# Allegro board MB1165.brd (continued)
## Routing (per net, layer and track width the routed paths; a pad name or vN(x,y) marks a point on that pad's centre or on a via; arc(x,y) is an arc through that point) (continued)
D10: length 138.4
  TOP w0.102: v4(72.52,100.6) 72.91,100.99 75.08,100.99 75.33,101.23 75.33,102.79 75.53,102.99 76.53,102.99 U9.F4 ; U16.C2 66.8,75.15 66.8,76.58 66.29,77.09 66.29,78.23 ; v5(87.46,76.97) U15.M2
  TOP w0.127: v5(66.29,79.25) 66.29,78.23 ; R62.2 v1(68.58,121.28) ; CN10.19 v3(53.42,105.97)
  L3_SIG w0.102: v4(72.52,100.6) 72,101.12 71.53,101.12 71.37,100.97 70.64,100.97 70.12,101.49 69.97,101.49 69.52,101.03 69.38,101.03 69.23,101.18 69.23,101.32 69.68,101.77 69.68,101.92 69.54,102.06 69.4,102.06 68.94,101.61 68.8,101.61 68.66,101.75 68.66,101.9 69.11,102.35 69.11,102.49 68.97,102.64 68.82,102.64 68.37,102.18 68.23,102.18 68.08,102.33 68.08,102.47 68.53,102.92 68.53,103.07 68.39,103.21 68.25,103.21 67.79,102.76 67.65,102.76 67.51,102.9 67.51,103.05 67.96,103.5 67.96,103.64 67.82,103.79 67.67,103.79 67.22,103.33 67.08,103.33 66.93,103.48 66.93,103.62 67.38,104.07 67.38,104.22 67.24,104.36 67.1,104.36 66.64,103.91 66.5,103.91 66.36,104.05 66.36,104.2 66.81,104.65 66.81,104.79 66.67,104.94 66.52,104.94 66.07,104.48 65.93,104.48 65.78,104.63 65.78,104.77 66.23,105.22 66.23,105.37 65.05,106.55 54,106.55 v3(53.42,105.97) ; v5(87.46,76.97) 86.45,77.98 86.45,78.17 85.75,78.87 74.55,78.87 v1(74.42,78.74) 66.42,78.74 66.29,78.87 v5(66.29,79.25)
  BOTTOM w0.127: v4(72.52,100.6) 72.52,98.81 69.98,96.27 69.98,90.78 70.1,90.65 70.48,90.65 70.61,90.53 70.61,90.32 70.48,90.2 70.13,90.2 70,90.07 70,89.87 70.13,89.74 70.46,89.74 70.59,89.61 70.59,89.43 70.46,89.31 70.1,89.31 69.98,89.18 69.98,88.85 70.1,88.72 70.89,88.72 71.02,88.85 71.02,90.53 71.15,90.65 71.35,90.65 71.48,90.53 71.48,88.85 71.6,88.72 71.81,88.72 71.93,88.85 71.93,90.53 72.06,90.65 72.31,90.65 72.44,90.53 72.44,88.85 72.57,88.72 72.82,88.72 72.95,88.85 72.95,90.53 73.08,90.65 73.33,90.65 73.46,90.53 73.46,88.04 73.58,87.91 73.84,87.91 73.96,88.04 73.96,90.53 74.09,90.65 74.3,90.65 74.42,90.53 v1(74.42,78.74) ; v3(53.42,105.97) 54.13,106.68 57.91,106.68 68.58,117.35 v1(68.58,121.28)
D11: length 139.5
  TOP w0.102: U9.G4 75.52,103.76 73.51,103.76 72.77,103.02 72.77,102.11 72.11,101.45 72.11,101.09 71.88,100.86 ; U16.D2 66.04,75.16 66.04,76.71 65.9,76.85 65.9,78.23 ; v5(85.86,77.77) U15.P1
  TOP w0.127: 65.9,78.23 65.9,78.56 65.34,79.12 v5(65.28,79.12) ; CN10.20 v3(54.86,105.97) ; R52.2 v1(68.58,124.59) ; 71.88,100.86 v4(71.65,100.63)
  L3_SIG w0.102: v4(71.65,100.63) 71.6,100.58 69.37,100.58 63.98,105.97 v3(54.86,105.97) ; v5(85.86,77.77) 85.86,78.28 85.58,78.56 74.86,78.56 74.52,78.23 v1(73.66,78.23) 73.46,78.44 66.14,78.44 65.46,79.12 v5(65.28,79.12)
  BOTTOM w0.127: v1(68.58,124.59) 68.58,124.05 68.71,123.93 69.01,123.93 69.14,123.8 69.14,123.6 69.01,123.47 68.68,123.47 68.55,123.34 68.55,123.11 68.68,122.98 68.99,122.98 69.11,122.85 69.11,122.6 68.99,122.47 68.68,122.47 68.55,122.35 68.55,122.12 68.68,122 69.09,122 69.22,121.87 69.22,117.35 57.84,105.97 v3(54.86,105.97) ; v1(73.66,78.23) 72.72,78.23 72.59,78.36 72.59,78.59 72.72,78.71 73.43,78.71 73.56,78.84 73.56,79.1 73.43,79.22 72.31,79.22 72.19,79.35 72.19,79.6 72.31,79.73 73.43,79.73 73.56,79.86 73.56,84.68 73.43,84.81 71.3,84.81 71.17,84.94 71.17,85.19 71.3,85.32 73.43,85.32 73.56,85.45 73.56,85.72 73.43,85.85 70.28,85.85 70.15,85.98 70.15,86.23 70.28,86.36 73.1,86.36 73.23,86.49 73.23,86.77 73.1,86.89 69.34,86.89 69.22,87.02 69.22,87.27 69.34,87.4 72.11,87.4 72.24,87.53 72.24,87.78 72.11,87.91 69.34,87.91 69.22,88.04 69.22,96.65 69.52,96.95 69.52,97.13 69.22,97.43 69.22,97.61 69.4,97.79 69.58,97.79 69.88,97.49 70.06,97.49 70.24,97.67 70.24,97.85 69.36,98.72 69.36,98.9 69.54,99.08 69.72,99.08 70.6,98.21 70.78,98.21 70.98,98.41 70.98,98.59 70.11,99.47 70.11,99.65 70.29,99.83 70.47,99.83 71.34,98.95 71.52,98.95 71.7,99.13 71.7,99.31 70.83,100.19 70.83,100.37 71.09,100.63 v4(71.65,100.63)
D12: length 135.8
  TOP w0.102: v5(64.84,77.28) 65.28,76.83 65.28,75.17 U16.E2 ; v5(86.66,76.97) U15.N2 ; U9.F5 76.51,102.77 75.67,102.77 75.53,102.63 75.53,101.11 75.19,100.76 73.33,100.76 v4(73.15,100.58)
  TOP w0.127: CN10.17 v3(53.42,107.24) ; R61.2 v1(67.56,121.28)
  L3_SIG w0.102: v5(86.66,76.97) 86.4,76.97 86.03,77.34 84.84,77.34 84.51,77.67 75.74,77.67 75.59,77.52 v1(74.93,77.52) 74.81,77.4 72.95,77.4 72.85,77.51 72.85,77.72 72.75,77.83 72.55,77.83 72.44,77.72 72.44,77.51 72.34,77.4 64.96,77.4 v5(64.84,77.28) ; v3(53.42,107.24) 52.83,106.65 52.83,105.69 53.09,105.44 55.47,105.44 55.57,105.33 55.57,104.42 55.67,104.32 55.9,104.32 56,104.42 56,105.51 56.11,105.61 56.31,105.61 56.41,105.51 56.41,104.42 56.51,104.32 56.72,104.32 56.82,104.42 56.82,105.51 56.92,105.61 57.12,105.61 57.22,105.51 57.22,104.42 57.33,104.32 57.53,104.32 57.63,104.42 57.63,105.51 57.73,105.61 57.94,105.61 58.04,105.51 58.04,104.42 58.14,104.32 58.34,104.32 58.44,104.42 58.44,105.51 58.54,105.61 58.75,105.61 58.85,105.51 58.85,104.42 58.95,104.32 59.15,104.32 59.26,104.42 59.26,105.51 59.36,105.61 59.56,105.61 59.66,105.51 59.66,104.42 59.76,104.32 59.97,104.32 60.07,104.42 60.07,105.51 60.17,105.61 60.37,105.61 60.48,105.51 60.48,104.42 60.58,104.32 60.78,104.32 60.88,104.42 60.88,105.51 60.98,105.61 61.19,105.61 61.29,105.51 61.29,104.42 61.39,104.32 61.59,104.32 61.69,104.42 61.69,105.51 61.8,105.61 62,105.61 62.1,105.51 62.1,104.42 62.2,104.32 62.41,104.32 62.51,104.42 62.51,105.51 62.61,105.61 62.81,105.61 62.91,105.51 62.91,104.42 63.02,104.32 63.22,104.32 63.32,104.42 63.32,105.51 63.42,105.61 63.62,105.61 63.73,105.51 63.73,104.42 63.83,104.32 65.02,104.32 69.14,100.2 72.77,100.2 v4(73.15,100.58)
  BOTTOM w0.127: v1(74.93,77.52) 74.93,90.91 74.8,91.03 70.48,91.03 70.36,91.16 70.36,96.06 73.15,98.86 v4(73.15,100.58) ; v3(53.42,107.24) 54.13,107.95 57.91,107.95 66.78,116.81 66.78,116.99 66.35,117.42 66.35,117.6 66.53,117.78 66.71,117.78 67.14,117.35 67.32,117.35 67.56,117.6 v1(67.56,121.28)
D13: length 147.3
  TOP w0.102: 74.15,97.79 75.29,98.93 75.29,100.44 75.91,101.06 U9.G6 ; v5(85.06,77.77) 85.06,77.93 84.93,78.05 84.27,78.05 ; U15.R1 84.27,77.37 ; U16.F2 64.52,75.18 64.52,76.22 64.52,76.22 64.52,76.83 v5(64.14,77.22)
  TOP w0.127: 84.27,78.05 84.15,78.05 84.02,77.93 84.02,77.49 84.15,77.37 84.27,77.37 ; CN10.35 53.03,95.81 v3(53.42,96.2) ; v4(73.03,96.65) 73.41,97.03 73.41,97.05 74.15,97.79 ; R56.2 v1(75.18,124.71)
  L3_SIG w0.102: v5(85.06,77.77) 85.37,77.77 85.5,77.89 85.5,78.13 85.37,78.26 84.76,78.26 84.63,78.13 84.63,78.11 84.51,77.98 84.21,77.98 84.11,78.08 84.11,78.16 84,78.26 83.8,78.26 83.7,78.16 83.7,78.08 83.6,77.98 83.39,77.98 83.29,78.08 83.29,78.16 83.19,78.26 82.99,78.26 82.89,78.16 82.89,78.08 82.79,77.98 82.58,77.98 82.48,78.08 82.48,78.16 82.38,78.26 82.18,78.26 82.07,78.16 82.07,78.08 81.97,77.98 81.77,77.98 81.67,78.08 81.67,78.16 81.57,78.26 81.36,78.26 81.26,78.16 81.26,78.08 81.16,77.98 80.96,77.98 80.85,78.08 80.85,78.16 80.75,78.26 80.55,78.26 80.45,78.16 80.45,78.08 80.35,77.98 80.14,77.98 80.04,78.08 80.04,78.16 79.94,78.26 79.74,78.26 79.64,78.16 79.64,78.08 79.53,77.98 79.33,77.98 79.23,78.08 79.23,78.16 79.13,78.26 78.92,78.26 78.82,78.16 78.82,78.08 78.72,77.98 78.52,77.98 78.42,78.08 78.42,78.16 78.31,78.26 78.11,78.26 78.01,78.16 78.01,78.08 77.91,77.98 77.09,77.98 v1(76.96,78.11) 74.9,78.11 74.56,77.76 73.42,77.76 73.05,78.13 72.24,78.13 71.87,77.76 64.55,77.76 64.14,77.34 v5(64.14,77.22) ; v4(73.03,96.65) 69.9,96.65 69.77,96.52 69.77,95.94 69.65,95.81 66.47,95.81 66.34,95.68 66.34,94.54 66.22,94.41 66.03,94.41 65.91,94.54 65.91,95.66 65.81,95.76 65.6,95.76 65.5,95.66 65.5,94.51 65.4,94.41 65.2,94.41 65.09,94.51 65.09,95.66 64.99,95.76 64.79,95.76 64.69,95.66 64.69,94.51 64.59,94.41 64.38,94.41 64.28,94.51 64.28,95.66 64.18,95.76 63.98,95.76 63.87,95.66 63.87,94.51 63.77,94.41 63.57,94.41 63.47,94.51 63.47,95.66 63.37,95.76 63.16,95.76 63.06,95.66 63.06,94.51 62.96,94.41 62.76,94.41 62.66,94.51 62.66,95.66 62.55,95.76 62.35,95.76 62.25,95.66 62.25,94.51 62.15,94.41 61.94,94.41 61.84,94.51 61.84,95.66 61.74,95.76 61.54,95.76 61.44,95.66 61.44,94.51 61.33,94.41 61.13,94.41 61.03,94.51 61.03,95.66 60.93,95.76 60.73,95.76 60.62,95.66 60.62,94.51 60.52,94.41 60.32,94.41 60.22,94.51 60.22,95.66 60.12,95.76 59.91,95.76 59.81,95.66 59.81,94.51 59.71,94.41 59.51,94.41 59.4,94.51 59.4,95.66 59.3,95.76 59.1,95.76 59,95.66 59,94.51 58.9,94.41 58.69,94.41 58.59,94.51 58.59,95.66 58.49,95.76 58.29,95.76 58.19,95.66 58.19,94.51 58.08,94.41 57.88,94.41 57.78,94.51 57.78,95.66 57.68,95.76 53.85,95.76 v3(53.42,96.2)
  BOTTOM w0.127: v1(75.18,124.71) 75.18,123.83 74.8,123.44 74.8,121.64 74.42,121.25 74.42,114.55 56.62,96.75 53.98,96.75 53.42,96.2 v3(53.42,96.2) ; v4(73.03,96.65) 73.03,96.11 76.96,92.18 v1(76.96,78.11)
D14: length 139.9
  TOP w0.102: v5(86.66,76.17) U15.N3 ; U9.F6 76.29,100.75 76.29,98.39 75.69,97.79 ; U16.F1 v5(64.92,76.07)
  TOP w0.127: v3(53.47,95.21) 53.47,95 53.01,94.54 CN10.37 ; R65.2 73.79,122.28 75.31,120.75 v1(75.44,120.75) ; 75.69,97.79 v4(74.55,96.65)
  L3_SIG w0.102: v5(86.66,76.17) 86.97,76.17 87.1,76.29 87.1,76.45 86.97,76.58 84.61,76.58 84.18,77.01 82.12,77.01 81.99,76.89 81.99,76.48 81.86,76.35 81.69,76.35 81.56,76.48 81.56,76.89 81.43,77.01 81.28,77.01 81.15,76.89 81.15,76.48 81.03,76.35 77.6,76.35 77.46,76.49 v1(77.46,76.85) 77.27,76.66 71.78,76.66 71.64,76.8 65.39,76.8 64.92,76.32 v5(64.92,76.07) ; v4(74.55,96.65) 74.55,95.1 74.42,94.97 74.12,94.97 73.99,95.1 73.99,96.15 73.86,96.28 73.62,96.28 73.52,96.18 73.52,95 73.41,94.89 73.21,94.89 73.11,95 73.11,96.07 72.99,96.19 72.82,96.19 72.7,96.07 72.7,95 72.6,94.89 72.4,94.89 72.3,95 72.3,96.18 72.2,96.28 71.99,96.28 71.89,96.18 71.89,95 71.79,94.89 71.59,94.89 71.48,95 71.48,96.18 71.38,96.28 70.21,96.28 70.08,96.15 70.08,94.21 69.95,94.08 69.72,94.08 69.62,94.18 69.62,95.4 69.52,95.5 69.31,95.5 69.21,95.4 69.21,94.18 69.11,94.08 68.91,94.08 68.81,94.18 68.81,95.4 68.7,95.5 68.5,95.5 68.4,95.4 68.4,94.18 68.3,94.08 68.09,94.08 67.99,94.18 67.99,95.4 67.89,95.5 67.69,95.5 67.59,95.4 67.59,94.18 67.49,94.08 67.28,94.08 67.18,94.18 67.18,95.4 67.08,95.5 66.88,95.5 66.77,95.4 66.77,94.18 66.67,94.08 57.43,94.08 57.3,94.21 57.3,95.33 57.18,95.45 53.71,95.45 v3(53.47,95.21)
  BOTTOM w0.127: v1(75.44,120.75) 75.18,120.5 75.18,114.17 56.64,95.63 53.89,95.63 v3(53.47,95.21) ; v4(74.55,96.65) 74.42,96.52 74.42,95.86 77.85,92.43 77.85,77.24 v1(77.46,76.85)
D15: length 138.8
  TOP w0.102: U16.G1 v5(64.16,76.07) ; U9.G7 75.53,99.99 75.53,98.39 74.93,97.79 ; v5(85.06,76.97) U15.R2
  TOP w0.127: 74.93,97.79 v4(73.84,96.7) ; CN10.36 55.24,95.81 54.86,96.19 v3(54.86,96.24) ; R66.2 75.18,121.67 v1(75.44,121.41)
  L3_SIG w0.102: v5(64.16,76.07) 64.16,76.1 65.15,77.09 76.81,77.09 v1(76.96,77.24) 77.06,77.34 77.9,77.34 78,77.24 78,76.78 78.1,76.68 78.3,76.68 78.4,76.78 78.4,77.25 78.52,77.37 78.69,77.37 78.81,77.25 78.81,76.78 78.91,76.68 79.12,76.68 79.22,76.78 79.22,77.25 79.34,77.37 79.5,77.37 79.62,77.25 79.62,76.78 79.72,76.68 79.91,76.68 80.04,76.81 80.04,77.14 80.16,77.27 80.34,77.27 80.47,77.14 80.47,76.81 80.59,76.68 80.72,76.68 80.85,76.81 80.85,77.21 80.98,77.34 84.36,77.34 84.73,76.97 v5(85.06,76.97) ; v4(73.84,96.7) 73.84,96.94 73.71,97.07 69.6,97.07 69.47,96.94 69.47,96.32 69.34,96.19 69.19,96.19 69.06,96.32 69.06,96.88 68.94,97 68.76,97 68.63,96.88 68.63,96.32 68.5,96.19 68.33,96.19 68.22,96.29 68.22,96.98 68.12,97.08 67.92,97.08 67.82,96.98 67.82,96.29 67.72,96.19 67.51,96.19 67.41,96.29 67.41,96.98 67.31,97.08 67.11,97.08 67.01,96.98 67.01,96.29 66.9,96.19 66.7,96.19 66.6,96.29 66.6,96.98 66.5,97.08 66.29,97.08 66.19,96.98 66.19,96.29 66.09,96.19 65.89,96.19 65.79,96.29 65.79,96.98 65.68,97.08 65.48,97.08 65.38,96.98 65.38,96.29 65.28,96.19 65.08,96.19 64.97,96.29 64.97,96.98 64.87,97.08 64.67,97.08 64.57,96.98 64.57,96.29 64.47,96.19 64.26,96.19 64.16,96.29 64.16,96.98 64.06,97.08 63.86,97.08 63.75,96.98 63.75,96.18 63.64,96.06 63.47,96.06 63.35,96.18 63.35,96.98 63.25,97.08 63.04,97.08 62.94,96.98 62.94,96.18 62.82,96.06 62.65,96.06 62.54,96.18 62.54,96.98 62.43,97.08 62.23,97.08 62.13,96.98 62.13,96.18 62.01,96.06 61.84,96.06 61.72,96.18 61.72,96.98 61.62,97.08 61.42,97.08 61.32,96.98 61.32,96.18 61.2,96.06 61.03,96.06 60.91,96.18 60.91,96.98 60.81,97.08 60.6,97.08 60.5,96.98 60.5,96.21 60.38,96.09 60.22,96.09 60.1,96.21 60.1,96.98 60,97.08 59.79,97.08 59.69,96.98 59.69,96.23 59.57,96.11 59.4,96.11 59.28,96.23 59.28,96.98 59.18,97.08 58.98,97.08 58.88,96.98 58.88,96.18 58.76,96.06 58.59,96.06 58.47,96.18 58.47,96.98 58.37,97.08 58.17,97.08 58.06,96.98 58.06,96.21 57.95,96.09 57.78,96.09 57.66,96.21 57.66,96.98 57.56,97.08 57.35,97.08 57.25,96.98 57.25,96.18 57.13,96.06 56.96,96.06 56.85,96.18 56.85,96.98 56.74,97.08 56.54,97.08 56.44,96.98 56.44,96.18 56.32,96.06 56.15,96.06 56.03,96.18 56.03,96.83 55.91,96.95 55.75,96.95 55.63,96.83 55.63,96.24 55.5,96.11 54.99,96.11 v3(54.86,96.24)
  BOTTOM w0.127: v3(54.86,96.24) 55.09,96.01 56.48,96.01 74.8,114.33 74.8,120.9 75.31,121.41 v1(75.44,121.41) ; v1(76.96,77.24) 77.09,77.24 77.47,77.62 77.47,92.22 73.79,95.9 73.79,96.65 v4(73.84,96.7)
D16: length 122.6
  TOP w0.102: 93.85,70.09 93.85,71.37 U15.E8
  TOP w0.127: v5(95.25,68.33) 93.85,69.72 93.85,70.09 ; R53.1 70.99,124.84 v1(70.87,124.71) ; CN10.22 v3(54.86,104.7)
  L3_SIG w0.102: v5(95.25,68.33) 92.3,68.33 88.9,64.92 66.62,64.92 51.66,79.88 51.66,84.56 51.77,84.66 53.73,84.66 53.85,84.78 53.85,84.95 53.73,85.07 51.77,85.07 51.66,85.17 51.66,85.37 51.77,85.47 52.92,85.47 53.04,85.59 53.04,85.76 52.92,85.88 51.77,85.88 51.66,85.98 51.66,86.19 51.77,86.29 52.08,86.29 52.2,86.41 52.2,86.57 52.08,86.69 51.77,86.69 51.66,86.8 51.66,104.17 52.63,105.13 54.03,105.13 54.46,104.7 v3(54.86,104.7)
  BOTTOM w0.127: v1(70.87,124.71) 70.15,124.71 69.98,124.54 69.98,116.74 57.93,104.7 v3(54.86,104.7)
D17: length 125
  TOP w0.102: v5(94.66,72.17) U15.D7
  TOP w0.127: R54.1 v1(72.39,124.71) ; CN10.26 v3(54.86,102.16)
  L3_SIG w0.102: v5(94.66,72.17) 95.07,71.75 95.78,71.75 95.89,71.65 95.89,71.12 96.27,70.74 96.27,69.98 95.76,69.47 92.51,69.47 88.6,65.56 66.95,65.56 52.32,80.19 52.32,80.57 52.43,80.67 54.08,80.67 54.2,80.79 54.2,80.96 54.08,81.08 52.43,81.08 52.32,81.18 52.32,81.38 52.43,81.48 54.16,81.48 54.28,81.6 54.28,81.77 54.16,81.89 52.43,81.89 52.32,81.99 52.32,82.19 52.43,82.3 54.36,82.3 54.46,82.4 54.46,85.32 52.27,87.5 52.27,102.06 52.96,102.74 53.59,102.74 54.18,102.16 v3(54.86,102.16)
  BOTTOM w0.127: v1(72.39,124.71) 72.39,124.46 71.88,123.95 71.88,120.65 71.5,120.27 71.5,115.95 57.71,102.16 v3(54.86,102.16)
D18: length 121.2
  TOP w0.102: U15.D8 94.7,71.32 94.7,70.09
  TOP w0.127: R63.1 v1(70.99,121.28) ; CN10.24 v3(54.86,103.43) ; v5(95.22,68.96) 95.22,69.24 94.7,69.76 94.7,70.09
  L3_SIG w0.102: v5(95.22,68.96) 92.46,68.96 88.72,65.23 66.83,65.23 51.97,80.09 51.97,82.62 52.07,82.72 54.05,82.72 54.15,82.82 54.15,83.02 54.05,83.12 52.07,83.12 51.97,83.22 51.97,83.43 52.07,83.53 54.05,83.53 54.15,83.63 54.15,83.83 54.05,83.94 52.07,83.94 51.97,84.04 51.97,84.24 52.07,84.34 54.05,84.34 54.15,84.44 54.15,85.12 51.97,87.3 51.97,103.15 52.83,104.01 53.59,104.01 54.18,103.43 v3(54.86,103.43)
  BOTTOM w0.127: v3(54.86,103.43) 57.81,103.43 70.74,116.36 70.74,121.03 v1(70.99,121.28)
D19: length 120.8
  TOP w0.102: v5(95.86,70.1) U15.B9
  TOP w0.127: R64.1 72.39,120.4 72,120 v1(72,119.9) ; CN10.27 v3(53.42,100.89)
  L3_SIG w0.102: v3(53.42,100.89) 52.58,100.05 52.58,87.73 54.79,85.52 54.79,85.23 54.89,85.13 55.71,85.13 55.83,85.01 55.83,84.85 55.71,84.73 54.89,84.73 54.79,84.62 54.79,84.42 54.89,84.32 55.8,84.32 55.91,84.22 55.91,84.02 55.8,83.91 54.89,83.91 54.79,83.81 54.79,83.61 54.89,83.51 55.8,83.51 55.91,83.41 55.91,83.2 55.8,83.1 54.89,83.1 54.79,83 54.79,82.8 54.89,82.69 55.8,82.69 55.91,82.59 55.91,82.39 55.8,82.29 54.89,82.29 54.79,82.19 54.79,81.98 54.89,81.88 55.8,81.88 55.91,81.78 55.91,81.58 55.8,81.48 54.89,81.48 54.79,81.37 54.79,80.34 54.69,80.24 53.13,80.24 53.01,80.12 53.01,79.95 53.13,79.83 54.69,79.83 54.79,79.73 54.79,79.53 54.69,79.42 54,79.42 53.9,79.32 53.9,79.12 54,79.02 54.69,79.02 54.79,78.92 54.79,78.16 67.08,65.86 88.47,65.86 92.46,69.85 95.61,69.85 v5(95.86,70.1)
  BOTTOM w0.127: v3(53.42,100.89) 54.13,101.6 57.73,101.6 72,115.86 v1(72,119.9)
D20: length 125.2
  TOP w0.102: v5(95.46,71.37) U15.C8
  TOP w0.127: CN10.32 v3(54.86,98.35) ; R55.1 v1(73.79,124.71)
  L3_SIG w0.102: v3(54.86,98.35) 54.15,99.06 53.42,99.06 52.88,98.53 52.88,88.57 56.21,85.24 56.21,81.23 56.11,81.13 55.19,81.13 55.09,81.02 55.09,80.82 55.19,80.72 56.5,80.72 56.62,80.6 56.62,80.43 56.5,80.31 55.19,80.31 55.09,80.21 55.09,80.01 55.19,79.91 56.45,79.91 56.57,79.79 56.57,79.62 56.45,79.5 55.19,79.5 55.09,79.4 55.09,79.2 55.19,79.09 56.42,79.09 56.54,78.98 56.54,78.81 56.42,78.69 55.19,78.69 55.09,78.59 55.09,78.38 55.19,78.28 56.36,78.28 56.54,78.11 56.54,76.91 67.21,66.24 88.37,66.24 92.25,70.13 92.25,71.48 92.38,71.6 92.66,71.6 92.79,71.48 92.79,70.82 92.91,70.69 93.17,70.69 93.29,70.82 93.29,71.48 93.42,71.6 93.63,71.6 93.76,71.48 93.76,70.76 93.86,70.66 94.06,70.66 94.16,70.76 94.16,71.51 94.28,71.63 94.45,71.63 94.57,71.51 94.57,70.76 94.67,70.66 94.88,70.66 94.98,70.76 94.98,71.27 95.08,71.37 v5(95.46,71.37)
  BOTTOM w0.127: v1(73.79,124.71) 73.79,124.15 73.27,123.63 73.27,115.44 56.18,98.35 v3(54.86,98.35)
D21: length 122.5
  TOP w0.102: v5(97.06,70.57) U15.A9
  TOP w0.127: v3(101.78,92.61) 101.78,92.6 101.11,93.27 CN11.39
  L3_SIG w0.102: v3(101.78,92.61) 102.87,91.52 102.87,90.81 98.93,86.87 98.93,83.97 98.81,83.85 97.79,83.85 97.66,83.72 97.66,73.38 96.65,72.36 96.65,70.98 v5(97.06,70.57)
  BOTTOM w0.127: R266.1 80.64,124.59 80.11,124.05 80.11,120.97 79.98,120.84 78.95,120.84 78.23,120.84 78.11,120.72 78.11,120.46 78.23,120.34 79.98,120.34 80.11,120.21 80.11,119.95 79.98,119.83 78.18,119.83 78.05,119.7 78.05,119.45 78.18,119.32 79.98,119.32 80.11,119.19 80.11,118.94 79.98,118.81 78.18,118.81 78.05,118.68 78.05,118.43 78.18,118.3 79.98,118.3 80.11,118.18 80.11,117.92 79.98,117.8 78.18,117.8 78.05,117.67 78.05,117.41 78.18,117.29 79.98,117.29 80.11,117.16 80.11,116.91 79.98,116.78 78.18,116.78 78.05,116.65 78.05,116.4 78.18,116.27 79.98,116.27 80.11,116.14 80.11,115.89 79.98,115.76 78.18,115.76 78.05,115.64 78.05,112.52 77.93,112.39 76.45,112.39 76.33,112.27 76.33,111.89 76.45,111.76 77.93,111.76 78.05,111.63 78.05,111.38 77.93,111.25 76.2,111.25 76.07,111.12 76.07,110.82 76.2,110.69 78.49,110.69 78.61,110.82 78.61,111.25 78.74,111.38 79.1,111.38 79.22,111.25 79.22,110.74 79.35,110.62 79.6,110.62 79.73,110.74 79.73,111.25 79.86,111.38 80.79,111.38 80.92,111.25 80.92,110.74 81.05,110.62 81.3,110.62 81.43,110.74 81.43,111.25 81.55,111.38 81.81,111.38 81.93,111.25 81.93,110.31 82.06,110.19 82.44,110.19 82.57,110.31 82.57,111.15 82.69,111.28 82.95,111.28 83.08,111.15 83.08,110.74 83.2,110.62 83.52,110.62 83.75,110.38 83.75,110.2 83.59,110.04 83.59,109.86 83.77,109.68 83.95,109.68 84.23,109.96 84.41,109.96 84.58,109.78 84.58,109.6 84.31,109.32 84.31,109.14 84.49,108.96 84.67,108.96 84.83,109.12 85.34,109.12 85.83,108.64 85.83,108.25 85.7,108.13 85.19,108.13 85.06,108 85.06,107.75 85.19,107.62 85.7,107.62 85.83,107.49 85.83,105.38 85.95,105.25 87.22,105.25 87.35,105.12 87.35,104.87 87.22,104.74 85.95,104.74 85.83,104.61 85.83,104.32 86,104.14 87.22,104.14 87.35,104.02 87.35,92.71 87.45,92.61 v3(101.78,92.61)
D22: length 118.6
  TOP w0.102: v5(95.46,72.17) U15.C7
  TOP w0.127: v3(103.5,95) 103.96,94.54 CN11.38
  L3_SIG w0.102: v3(103.5,95) 103,95.5 101.73,95.5 99.77,93.55 99.77,93.19 100.53,92.43 100.53,92.08 97.43,88.98 97.43,85.85 97.31,85.72 96.83,85.72 96.7,85.6 96.7,75.5 96.8,75.4 97.1,75.4 97.21,75.3 97.21,75.1 97.1,74.99 96.8,74.99 96.7,74.89 96.7,74.69 96.8,74.59 97.1,74.59 97.21,74.49 97.21,74.28 97.1,74.18 96.8,74.18 96.7,74.08 96.7,73.41 v5(95.46,72.17)
  BOTTOM w0.127: v3(103.5,95) 103.89,94.61 103.89,93.47 103.25,92.84 102.26,92.84 101.85,93.24 101.52,93.24 101.37,93.09 87.88,93.09 87.76,93.22 87.76,93.45 87.88,93.57 89.36,93.57 89.48,93.7 89.48,94.04 89.36,94.17 87.88,94.17 87.76,94.29 87.76,94.55 87.88,94.67 89.36,94.67 89.48,94.8 89.48,95.05 89.36,95.18 87.88,95.18 87.76,95.31 87.76,95.56 87.88,95.69 89.36,95.69 89.48,95.82 89.48,96.07 89.36,96.2 87.88,96.2 87.76,96.32 87.76,96.58 87.88,96.71 89.36,96.71 89.48,96.83 89.48,101.52 89.36,101.65 87.91,101.65 87.78,101.78 87.78,105.28 87.39,105.67 86.39,105.67 86.26,105.8 86.26,108.81 83.29,111.79 78.56,111.79 78.44,111.91 78.44,112.17 78.56,112.29 82.3,112.29 82.42,112.42 82.42,112.65 82.3,112.78 78.56,112.78 78.44,112.9 78.44,113.2 78.56,113.33 80.75,113.33 80.87,113.45 80.87,113.71 80.75,113.84 78.56,113.84 78.44,113.96 78.44,114.22 78.56,114.34 80.72,114.34 80.85,114.47 80.85,114.72 80.72,114.85 78.56,114.85 78.44,114.98 78.44,115.23 78.56,115.36 80.52,115.36 80.64,115.49 R276.1
D23: length 118.5
  TOP w0.102: v5(97.06,71.37) U15.A8
  TOP w0.127: CN11.36 103.71,95.81 v3(103.5,96.01)
  L3_SIG w0.102: v5(97.06,71.37) 98.04,72.35 98.04,83.36 98.17,83.49 99.16,83.49 99.29,83.62 99.29,86.59 104.17,91.47 104.17,95.61 103.76,96.01 v3(103.5,96.01)
  BOTTOM w0.127: v3(103.5,96.01) 103.38,96.01 102.87,95.5 101.22,95.5 101.09,95.38 101.09,94.03 100.97,93.9 98.41,93.9 98.29,94.03 98.29,95.38 98.16,95.5 97.91,95.5 97.78,95.38 97.78,94.03 97.65,93.9 97.4,93.9 97.27,94.03 97.27,95.38 97.14,95.5 96.89,95.5 96.76,95.38 96.76,94.03 96.64,93.9 96.38,93.9 96.25,94.03 96.25,95.38 96.13,95.5 95.87,95.5 95.75,95.38 95.75,94.03 95.62,93.9 95.37,93.9 95.24,94.03 95.24,95.38 95.11,95.5 94.86,95.5 94.73,95.38 94.73,94.03 94.6,93.9 94.35,93.9 94.22,94.03 94.22,95.38 94.1,95.5 93.84,95.5 93.71,95.38 93.71,94.03 93.59,93.9 93.33,93.9 93.21,94.03 93.21,95.38 93.08,95.5 92.83,95.5 92.7,95.38 92.7,94.03 92.57,93.9 92.32,93.9 92.19,94.03 92.19,95.38 92.06,95.5 91.11,95.5 90.98,95.63 90.98,102.44 90.86,102.56 90.4,102.56 90.27,102.69 90.27,102.94 90.4,103.07 90.86,103.07 90.98,103.2 90.98,103.89 90.86,104.01 90.09,104.01 89.97,104.14 89.97,104.42 90.09,104.55 90.63,104.55 90.76,104.67 90.76,104.95 90.63,105.08 90.09,105.08 89.97,105.21 89.97,105.46 90.09,105.59 90.71,105.59 91.06,105.94 91.06,106.12 90.88,106.3 90.7,106.3 90.4,106 90.22,106 90.04,106.18 90.04,106.36 90.34,106.66 90.34,106.84 90.16,107.02 89.98,107.02 89.68,106.72 89.5,106.72 89.32,106.89 89.32,107.07 89.62,107.38 89.62,107.56 89.44,107.74 89.26,107.74 88.96,107.43 88.78,107.43 88.6,107.61 88.6,107.79 88.9,108.1 88.9,108.28 88.72,108.46 88.54,108.46 88.24,108.15 88.06,108.15 87.88,108.33 87.88,108.51 88.19,108.81 88.19,108.99 88.01,109.17 87.83,109.17 87.52,108.87 87.34,108.87 87.16,109.05 87.16,109.23 87.47,109.53 87.47,109.71 87.29,109.89 87.11,109.89 86.8,109.59 86.62,109.59 86.45,109.77 86.45,109.95 86.75,110.25 86.75,110.43 86.57,110.61 86.39,110.61 86.09,110.31 85.91,110.31 85.73,110.49 85.73,110.67 86.03,110.97 86.03,111.15 85.85,111.33 85.67,111.33 85.37,111.03 85.19,111.03 85.01,111.21 85.01,111.39 85.31,111.69 85.31,111.87 85.13,112.05 84.95,112.05 84.65,111.75 84.47,111.75 84.29,111.93 84.29,112.11 84.59,112.41 84.59,112.59 84.41,112.77 84.23,112.77 83.93,112.47 83.75,112.47 83.57,112.65 83.57,112.83 83.87,113.13 83.87,113.31 83.69,113.49 83.51,113.49 83.21,113.18 83.03,113.18 82.85,113.36 82.85,113.54 83.15,113.85 83.15,114.03 82.52,114.66 82.52,115.49 82.4,115.62 81.81,115.62 81.69,115.75 81.69,116 81.81,116.13 82.4,116.13 82.52,116.26 82.52,116.51 82.4,116.64 81.81,116.64 81.69,116.76 81.69,117.02 81.81,117.14 82.4,117.14 82.52,117.27 82.52,117.53 82.4,117.65 81.81,117.65 81.69,117.78 81.69,118.03 81.81,118.16 82.4,118.16 82.52,118.29 82.52,118.54 82.4,118.67 81.81,118.67 81.69,118.8 81.69,119.05 81.81,119.18 82.4,119.18 82.52,119.3 82.52,119.56 82.4,119.68 81.81,119.68 81.69,119.81 81.69,120.07 81.81,120.19 82.4,120.19 82.52,120.32 82.52,120.57 82.4,120.7 81.81,120.7 81.69,120.83 81.69,121.08 81.81,121.21 82.4,121.21 82.52,121.34 82.52,121.69 82.42,121.79 R275.1
D24: length 124.1
  TOP w0.127: U15.A2 97.2,77.11 v5(97.28,77.11) ; CN11.37 101.52,94.54 101.85,94.87 101.85,94.88 v3(101.98,95.01)
  L3_SIG w0.102: v3(101.98,95.01) 101.94,95.01 100.91,93.97 100.91,93.83 101.46,93.27 101.46,93.1 101.34,92.98 101.17,92.98 100.62,93.54 100.47,93.54 100.33,93.4 100.33,93.25 102.51,91.07 102.51,90.96 102.25,90.69 102.11,90.69 100.94,91.86 100.8,91.86 100.66,91.71 100.66,91.57 101.82,90.41 101.82,90.26 101.68,90.12 101.53,90.12 100.37,91.28 100.22,91.28 100.08,91.14 100.08,91 101.24,89.83 101.24,89.69 101.1,89.54 100.96,89.54 99.79,90.71 99.65,90.71 99.51,90.56 99.51,90.42 100.67,89.26 100.67,89.11 100.53,88.97 100.38,88.97 99.22,90.13 99.07,90.13 98.93,89.99 98.93,89.85 100.09,88.68 100.09,88.54 99.95,88.39 99.81,88.39 98.64,89.56 98.5,89.56 98.35,89.41 98.35,89.27 99.52,88.11 99.52,87.96 99.38,87.82 99.23,87.82 98.07,88.98 97.92,88.98 97.78,88.84 97.78,88.7 98.94,87.53 98.94,87.39 98.6,87.05 98.6,85.45 98.48,85.32 97.16,85.32 97.03,85.19 97.03,77.36 v5(97.28,77.11)
  BOTTOM w0.127: R265.1 82.17,125.09 82.17,123.95 81.28,123.06 81.28,114.38 86.66,108.99 86.66,108.31 86.79,108.18 87.43,108.18 87.55,108.05 87.55,107.8 87.43,107.67 86.79,107.67 86.66,107.54 86.66,107.29 86.79,107.16 88.49,107.16 88.62,107.04 88.62,106.78 88.49,106.65 86.79,106.65 86.66,106.53 86.66,106.22 86.79,106.1 89.41,106.1 89.53,105.97 89.53,105.66 89.41,105.54 88.32,105.54 88.19,105.41 88.19,105.16 88.32,105.03 89.41,105.03 89.53,104.9 89.53,104.65 89.41,104.52 88.32,104.52 88.19,104.39 88.19,104.14 88.32,104.01 89.41,104.01 89.53,103.89 89.53,103.63 89.41,103.51 88.32,103.51 88.19,103.38 88.19,103.12 88.32,103 89.41,103 89.53,102.87 89.53,102.62 89.41,102.49 88.32,102.49 88.19,102.36 88.19,102.16 88.32,102.03 90.42,102.03 90.55,101.9 90.55,100.92 90.42,100.79 90.02,100.79 89.89,100.67 89.89,100.41 90.02,100.29 90.45,100.29 90.58,100.16 90.58,99.9 90.45,99.78 90.02,99.78 89.89,99.65 89.89,99.4 90.02,99.27 90.45,99.27 90.58,99.14 90.58,98.89 90.45,98.76 90.02,98.76 89.89,98.63 89.89,98.38 90.02,98.25 90.45,98.25 90.58,98.13 90.58,97.87 90.45,97.75 90.02,97.75 89.89,97.62 89.89,97.36 90.02,97.24 90.45,97.24 90.58,97.11 90.58,96.86 90.45,96.73 90.02,96.73 89.89,96.6 89.89,96.35 90.02,96.22 90.45,96.22 90.58,96.09 90.58,95.84 90.45,95.71 90.02,95.71 89.89,95.59 89.89,95.33 90.02,95.21 90.45,95.21 90.58,95.08 90.58,94.82 90.45,94.7 90.02,94.7 89.89,94.57 89.89,94.32 90.02,94.19 90.45,94.19 90.58,94.06 90.58,93.62 90.7,93.5 90.97,93.5 91.1,93.62 91.1,95 91.23,95.12 91.48,95.12 91.61,95 91.61,93.62 91.74,93.5 101.22,93.5 101.47,93.75 101.47,94.92 101.55,95 101.97,95 v3(101.98,95.01)
D25: length 122.8
  TOP w0.102: v5(95.46,76.17) U15.C3
  TOP w0.127: v3(101.98,96.01) 101.78,95.81 CN11.35
  L3_SIG w0.102: v3(101.98,96.01) 101.7,96.01 99.34,93.65 99.34,93.14 99.97,92.51 99.97,92 97.09,89.12 97.09,86.18 96.96,86.06 96.42,86.06 96.29,85.93 96.29,77.5 95.9,77.12 95.9,74.4 95.78,74.27 95.59,74.27 95.46,74.4 v5(95.46,76.17)
  BOTTOM w0.127: v3(101.98,96.01) 101.3,96.01 101.17,96.14 101.17,96.6 101.04,96.72 100.79,96.72 100.66,96.6 100.66,94.44 100.53,94.31 100.18,94.31 100.05,94.44 100.05,97.71 99.92,97.84 99.67,97.84 99.54,97.71 99.54,94.44 99.42,94.31 98.88,94.31 98.76,94.44 98.76,98.73 98.63,98.86 98.35,98.86 98.22,98.73 98.22,96.14 98.09,96.01 97.78,96.01 97.65,96.14 97.65,98.76 97.52,98.88 97.27,98.88 97.14,98.76 97.14,96.14 97.01,96.01 96.76,96.01 96.63,96.14 96.63,98.76 96.51,98.88 96.25,98.88 96.13,98.76 96.13,96.14 96,96.01 95.74,96.01 95.62,96.14 95.62,98.76 95.49,98.88 95.24,98.88 95.11,98.76 95.11,96.14 94.98,96.01 94.73,96.01 94.6,96.14 94.6,98.76 94.47,98.88 94.22,98.88 94.09,98.76 94.09,96.14 93.97,96.01 93.71,96.01 93.59,96.14 93.59,98.76 93.46,98.88 93.2,98.88 93.08,98.76 93.08,96.14 92.95,96.01 92.7,96.01 92.57,96.14 92.57,98.76 92.44,98.88 92.19,98.88 92.06,98.76 92.06,96.14 91.93,96.01 91.59,96.01 91.47,96.14 91.47,106.3 82.93,114.83 82.93,124.71 R264.1
D26: length 122.6
  TOP w0.127: CN11.33 v3(102.03,97.08) ; v1(98.55,77.22) 98.17,77.6 96.9,77.6 96.67,77.37 U15.A1
  L3_SIG w0.102: v1(98.55,77.22) 98.55,82.09 98.68,82.22 99.44,82.22 99.57,82.35 99.57,82.55 99.44,82.68 98.53,82.68 98.4,82.8 98.4,83.01 98.53,83.13 99.56,83.13 99.68,83.26 99.68,86.53 104.6,91.44 104.6,99.69 104.47,99.82 104.22,99.82 104.09,99.69 104.09,97.87 103.96,97.74 103.07,97.74 102.95,97.61 102.95,97.21 102.82,97.08 v3(102.03,97.08)
  BOTTOM w0.127: v3(102.03,97.08) 101.8,97.08 96.6,102.29 95.59,102.29 95.46,102.41 95.46,103.58 95.33,103.71 95.08,103.71 94.95,103.58 94.95,102.41 94.83,102.29 94.57,102.29 94.45,102.41 94.45,104.6 94.32,104.72 94.06,104.72 93.94,104.6 93.94,102.41 93.81,102.29 93.56,102.29 93.43,102.41 93.43,105.74 93.3,105.87 93.05,105.87 92.92,105.74 92.92,102.39 92.79,102.26 92.35,102.26 92.23,102.39 92.23,106.65 86.49,112.39 86.49,112.84 86.36,112.97 85.9,112.97 85.78,113.1 85.78,113.35 85.9,113.48 86.49,113.48 86.61,113.61 86.61,113.86 86.49,113.99 86.13,113.99 86,114.11 86,114.37 86.13,114.5 86.49,114.5 86.61,114.62 86.61,114.88 86.49,115 84.07,115 83.95,115.13 83.95,115.38 84.07,115.51 86.49,115.51 86.61,115.64 86.61,115.89 86.49,116.02 84.1,116.02 83.97,116.15 83.97,116.4 84.1,116.53 86.49,116.53 86.61,116.65 86.61,116.91 86.49,117.04 84.1,117.04 83.97,117.16 83.97,117.42 84.1,117.54 86.49,117.54 86.61,117.67 86.61,117.92 86.49,118.05 84.07,118.05 83.95,118.18 83.95,118.43 84.07,118.56 86.49,118.56 86.61,118.69 86.61,118.94 86.49,119.07 84.07,119.07 83.95,119.19 83.95,119.45 84.07,119.58 86.49,119.58 86.61,119.7 86.61,119.96 86.49,120.08 84.07,120.08 83.95,120.21 83.95,120.46 84.07,120.59 86.49,120.59 86.61,120.72 86.61,120.93 86.49,121.06 84.45,121.06 84.33,121.18 84.33,124.71 R263.1
D27: length 118.9
  TOP w0.102: v5(95.46,76.97) U15.C2
  TOP w0.127: CN11.34 v3(103.5,97.08)
  L3_SIG w0.102: v3(103.5,97.08) 103.5,96.75 103.28,96.52 101.53,96.52 101.1,96.95 100.96,96.95 100.81,96.8 100.81,96.66 101.26,96.22 101.26,96.07 101.11,95.93 100.97,95.93 100.53,96.37 100.38,96.37 100.24,96.23 100.24,96.08 100.68,95.64 100.68,95.5 100.54,95.35 100.39,95.35 99.95,95.8 99.81,95.8 99.66,95.65 99.66,95.51 100.11,95.07 100.11,94.92 99.96,94.78 99.82,94.78 99.38,95.22 99.23,95.22 99.09,95.08 99.09,94.93 99.53,94.49 99.53,94.35 99.39,94.2 99.24,94.2 98.8,94.65 98.66,94.65 98.51,94.5 98.51,94.36 98.96,93.92 98.96,93.77 98.81,93.63 98.67,93.63 98.23,94.07 98.08,94.07 97.94,93.93 97.94,93.78 99.45,92.27 99.45,91.94 99.29,91.77 99.14,91.77 97.74,93.17 97.59,93.17 97.45,93.03 97.45,92.89 98.85,91.48 98.85,91.34 98.71,91.19 98.57,91.19 97.16,92.6 97.02,92.6 96.87,92.45 96.87,92.31 98.28,90.9 98.28,90.76 98.14,90.62 97.99,90.62 96.59,92.02 96.44,92.02 96.3,91.88 96.3,91.74 97.7,90.33 97.7,90.19 96.99,89.47 94.77,89.47 94.67,89.37 94.67,89.16 94.77,89.06 95.83,89.06 95.94,88.96 95.94,88.76 95.83,88.65 94.77,88.65 94.67,88.55 94.67,88.35 94.77,88.25 95.83,88.25 95.94,88.15 95.94,87.94 95.83,87.84 94.77,87.84 94.67,87.74 94.67,87.54 94.77,87.43 95.83,87.43 95.94,87.33 95.94,77.67 95.46,77.2 v5(95.46,76.97)
  BOTTOM w0.127: v3(103.5,97.08) 103.05,97.08 102.49,96.52 101.8,96.52 98.98,99.34 98.08,99.34 97.95,99.47 97.95,100.3 97.82,100.43 97.57,100.43 97.44,100.3 97.44,99.47 97.32,99.34 97.06,99.34 96.94,99.47 96.94,101.17 96.81,101.3 96.55,101.3 96.43,101.17 96.43,99.47 96.3,99.34 96.05,99.34 95.92,99.47 95.92,101.63 95.79,101.75 95.54,101.75 95.41,101.63 95.41,99.47 95.28,99.34 95.03,99.34 94.9,99.47 94.9,101.63 94.78,101.75 94.52,101.75 94.4,101.63 94.4,99.47 94.27,99.34 94.01,99.34 93.89,99.47 93.89,101.63 93.76,101.75 93.51,101.75 93.38,101.63 93.38,99.47 93.25,99.34 93,99.34 92.87,99.47 92.87,101.63 92.74,101.75 92.49,101.75 92.36,101.63 92.36,99.47 92.24,99.34 91.97,99.34 91.85,99.47 91.85,106.48 83.36,114.96 83.36,121.01 83.57,121.21 R274.1
D28: length 118
  TOP w0.127: U15.B1 96.6,78.11 98.6,78.11 99.42,77.29 v5(99.42,77.27) ; CN11.22 v3(103.38,104.7)
  L3_SIG w0.102: v3(103.38,104.7) 103.73,104.7 103.86,104.57 103.86,102.52 103.96,102.41 105.32,102.41 105.44,102.3 105.44,102.13 105.32,102.01 103.96,102.01 103.86,101.91 103.86,101.7 103.96,101.6 105.31,101.6 105.41,101.5 105.41,101.3 105.31,101.2 103.96,101.2 103.86,101.09 103.86,100.79 103.99,100.66 105.23,100.66 105.36,100.53 105.36,87.02 105.23,86.89 105.04,86.89 104.92,87.02 104.92,90.2 104.8,90.32 104.63,90.32 104.51,90.2 104.51,86.68 104.39,86.56 104.22,86.56 104.1,86.68 104.1,89.47 103.98,89.59 103.82,89.59 103.7,89.47 103.7,85.36 103.58,85.24 103.41,85.24 103.29,85.36 103.29,88.73 103.17,88.85 103,88.85 102.88,88.73 102.88,84.65 102.77,84.53 102.6,84.53 102.48,84.65 102.48,87.89 102.36,88.01 102.19,88.01 102.07,87.89 102.07,84.55 101.95,84.43 101.78,84.43 101.67,84.55 101.67,86.98 101.55,87.1 101.38,87.1 101.26,86.98 101.26,84.52 101.14,84.4 100.97,84.4 100.85,84.52 100.85,86.22 100.73,86.33 100.56,86.33 100.45,86.22 100.45,82.23 99.42,81.2 v5(99.42,77.27)
  BOTTOM w0.127: R247.1 90.3,133.6 90.3,126.24 90.81,125.73 90.81,114.65 101.37,104.09 102.44,104.09 103.05,104.7 v3(103.38,104.7)
D29: length 119.4
  TOP w0.102: 97.73,75.06 95.12,75.06 94.61,75.56 94.61,76.21 U15.D2
  TOP w0.127: CN11.18 v3(103.38,107.24) ; v1(98.81,76.2) 98.81,75.82 98.04,75.06 97.73,75.06
  L3_SIG w0.102: v3(103.38,107.24) 104.83,107.24 106.4,105.66 106.4,88.82 107.11,88.11 107.11,84.02 106.4,83.31 106.4,78.87 106.27,78.74 105.94,78.74 105.81,78.61 105.81,78.38 105.91,78.28 106.38,78.28 106.48,78.18 106.48,77.98 106.38,77.88 105.91,77.88 105.81,77.77 105.81,77.57 105.91,77.47 106.38,77.47 106.48,77.37 106.48,77.17 106.38,77.06 105.91,77.06 105.81,76.96 105.81,75.36 105.71,75.26 105.5,75.26 105.4,75.36 105.4,76.87 105.28,76.99 105.12,76.99 105,76.87 105,75.36 104.9,75.26 104.69,75.26 104.59,75.36 104.59,75.8 104.47,75.92 104.3,75.92 104.18,75.8 104.18,75.36 104.08,75.26 103.94,75.26 103.81,75.39 103.81,78.62 103.69,78.74 103.52,78.74 103.4,78.62 103.4,76.86 103.28,76.73 103.05,76.73 102.92,76.86 102.92,78.61 102.79,78.74 102.57,78.74 102.44,78.61 102.44,75.39 102.31,75.26 102.16,75.26 102.03,75.39 102.03,75.82 101.9,75.95 101.67,75.95 101.54,75.82 101.54,75.39 101.42,75.26 99.44,75.26 99.26,75.08 99.26,70.61 99.14,70.48 98.93,70.48 98.81,70.61 v1(98.81,76.2)
  BOTTOM w0.127: v3(103.38,107.24) 102.79,106.65 101.55,106.65 93.34,114.86 93.34,115.39 93.22,115.52 92.71,115.52 92.58,115.65 92.58,115.87 92.71,116 93.24,116 93.37,116.13 93.37,116.38 93.24,116.51 92.71,116.51 92.58,116.64 92.58,116.89 92.71,117.02 93.24,117.02 93.37,117.14 93.37,117.4 93.24,117.53 92.71,117.53 92.58,117.65 92.58,117.88 92.71,118.01 93.14,118.01 93.27,118.14 93.27,118.41 93.14,118.54 92.71,118.54 92.58,118.67 92.58,135.13 R240.1
D30: length 118.2
  TOP w0.102: 97.73,74.68 94.87,74.68 94.26,75.29 U15.D3
  TOP w0.127: CN11.20 v3(103.38,105.97) ; v1(99.31,75.69) 98.3,74.68 97.73,74.68
  L3_SIG w0.102: v1(99.31,75.69) 99.44,75.56 100,75.56 100.13,75.69 100.13,78.44 100.25,78.56 100.46,78.56 100.58,78.44 100.58,75.74 100.71,75.62 100.86,75.62 100.99,75.74 100.99,80.77 101.12,80.9 101.32,80.9 101.45,80.77 101.45,77.17 101.57,77.04 101.8,77.04 101.93,77.17 101.93,79.07 102.06,79.2 104.01,79.2 104.14,79.07 104.14,77.19 104.27,77.06 104.44,77.06 104.57,77.19 104.57,79.05 104.7,79.17 104.88,79.17 105,79.05 105,77.55 105.13,77.42 105.31,77.42 105.44,77.55 105.44,78.97 105.56,79.1 105.94,79.1 106.07,79.22 106.07,79.43 105.94,79.55 102.03,79.55 101.9,79.68 101.9,80.67 102.03,80.8 102.26,80.8 102.39,80.67 102.39,80.09 102.51,79.96 102.77,79.96 102.9,80.09 102.9,80.67 103.02,80.8 104.19,80.8 104.32,80.67 104.32,80.04 104.44,79.91 104.7,79.91 104.83,80.04 104.83,80.75 104.95,80.87 105.36,80.87 105.49,80.75 105.49,80.04 105.61,79.91 105.94,79.91 106.07,80.04 106.07,105.38 105.49,105.97 v3(103.38,105.97)
  BOTTOM w0.127: R241.1 91.57,135.13 91.57,132.21 91.06,131.7 91.06,126.87 91.57,126.36 91.57,115.19 101.42,105.33 102.74,105.33 v3(103.38,105.97)
D31: length 119.9
  TOP w0.102: 97.73,74.17 95,74.17 93.85,75.31 93.85,76.17 U15.E2
  TOP w0.127: v1(99.57,76.3) 99.59,76.3 99.85,76.05 99.85,75.59 98.42,74.17 97.73,74.17 ; CN11.21 v3(101.98,104.7)
  L3_SIG w0.102: v3(101.98,104.7) 101.98,105.22 102.04,105.28 105.56,105.28 105.74,105.11 105.74,104.9 105.64,104.8 104.29,104.8 104.19,104.7 104.19,104.5 104.29,104.4 105.64,104.4 105.74,104.29 105.74,104.09 105.64,103.99 104.29,103.99 104.19,103.89 104.19,103.68 104.29,103.58 105.64,103.58 105.74,103.48 105.74,103.28 105.64,103.18 104.29,103.18 104.19,103.07 104.19,102.87 104.29,102.77 105.64,102.77 105.74,102.67 105.74,86.82 105.13,86.21 105.13,81.36 105,81.23 104.78,81.23 104.67,81.33 104.67,83.79 104.57,83.9 104.37,83.9 104.27,83.79 104.27,81.33 104.17,81.23 103.96,81.23 103.86,81.33 103.86,83.79 103.76,83.9 103.56,83.9 103.45,83.79 103.45,81.33 103.35,81.23 103.15,81.23 103.05,81.33 103.05,83.79 102.95,83.9 102.74,83.9 102.64,83.79 102.64,81.33 102.54,81.23 102.34,81.23 102.23,81.33 102.23,83.79 102.13,83.9 101.93,83.9 101.83,83.79 101.83,81.33 101.73,81.23 101.52,81.23 101.42,81.33 101.42,83.79 101.32,83.9 101.12,83.9 101.02,83.79 101.02,81.33 100.91,81.23 99.92,81.23 99.8,81.1 99.8,76.53 v1(99.57,76.3)
  BOTTOM w0.127: v3(101.98,104.7) 101.93,104.65 101.35,104.65 91.19,114.81 91.19,126.11 90.68,126.62 90.68,131.95 91.19,132.46 91.19,134.49 R244.1
DSI_VDD12: length 14.5
  TOP w0.381: U4.K12 76.77,134.09 v5(76.41,134.44) ; U4.G13 v5(79.61,132.89)
  TOP w0.508: C31.1 76.96,127.46 v1(77.53,128.03)
  BOTTOM w0.127: 77.41,132.09 77.41,132.17 76.8,132.78 76.8,134.06 76.71,134.14
  BOTTOM w0.381: v5(76.41,134.44) 76.71,134.14
  BOTTOM w0.508: C141.1 C140.1 78.11,132.21 ; v1(77.53,128.03) 77.53,129.4 77.41,129.52 77.41,132.09 77.53,132.21 78.11,132.21 ; 78.11,132.21 78.93,132.21 v5(79.61,132.89)
E5V: length 42.2
  TOP w0.508: D12.1 v1(26.82,72.14) ; 2.91,55.21 L5.3 ; L5.3 5.3,55.21 ; L5.3 4.1,56.4 ; 3.61,65.15 4.57,65.15 ; 4.57,65.15 4.57,66.12 ; 4.57,65.15 4.57,64.19 ; 4.57,65.15 5.54,65.15 ; 18.03,55.55 C60.1 ; C60.1 15.29,57.28 ; C60.1 18.03,59
  BOTTOM w0.508: 4.57,65.15 5.84,66.42 22.23,66.42 26.54,70.74 26.54,71.86 v1(26.82,72.14)
I2C1_SCL_C: length 8.7
  TOP w0.127: v1(151.26,151.26) 150.69,150.69 CN4.13
  BOTTOM w0.127: T5.2 154.05,153.65 R295.2 R219.1 153.29,151.38 151.38,151.38 v1(151.26,151.26)
I2C1_SDA_C: length 6.9
  TOP w0.127: CN4.14 151.42,150.69 v1(151.23,150.5)
  BOTTOM w0.127: T6.2 149.73,153.14 R296.2 150.24,151.76 150.24,151.38 151.13,150.5 v1(151.23,150.5) 151.35,150.62 R224.1
LCD_B0: length 165
  TOP w0.127: v1(112.12,140.92) 112.12,140.46 111.1,139.45 CN6.27 ; v5(85.7,134.92) 85.27,135.36 84.51,135.36 84.43,135.27 83.63,135.27 U4.B10 ; v1(80.96,46.35) CN18.21
  L3_SIG w0.102: v1(112.12,140.92) 111.89,141.15 110.41,141.15 109.32,140.06 99.92,140.06 94.11,134.24 88.27,134.24 87.81,133.78 86.41,133.78 85.7,134.49 v5(85.7,134.92)
  BOTTOM w0.127: v1(112.12,140.92) 112.93,140.11 116.84,140.11 120.93,136.02 120.93,127.91 121.64,127.2 121.64,123.09 120.7,122.15 120.7,118.77 115.01,113.08 115.01,86 116.84,84.18 116.84,75.62 95.16,53.94 95.16,49.06 91.19,45.09 82.23,45.09 v1(80.96,46.35)
LCD_B1: length 221.4
  TOP w0.102: v5(82.01,138.49) U4.C7
  TOP w0.127: CN18.23 79.69,42.86 80.01,42.55 v1(84.33,42.55) ; v1(111.86,148.34) 111.86,147.83 111.1,147.07 CN6.15
  L3_SIG w0.102: v1(84.33,42.55) 90.32,36.55 110.26,36.55 112.75,39.04 112.75,53.82 113.64,54.71 113.64,74.75 118.01,79.12 118.01,88.7 123.52,94.21 125.48,94.21 126.72,95.45 126.72,96.37 132.16,101.8 132.16,105.03 134.06,106.93 v1(134.19,106.93) ; v1(128.37,152.12) 127.41,151.16 118.26,151.16 114.83,147.73 113.49,147.73 112.88,148.34 v1(111.86,148.34) 110.87,148.34 109.35,146.81 96.14,146.81 92.08,142.75 90.81,142.75 88.27,140.21 85.09,140.21 82.93,138.05 82.45,138.05 v5(82.01,138.49)
  BOTTOM w0.127: v1(134.19,106.93) 134.16,106.93 133.86,107.24 133.86,107.54 133.83,107.56 133.83,118.59 135.46,120.22 135.46,125.22 131.17,129.51 131.17,149.33 v1(128.37,152.12)
LCD_B2: length 182.8
  TOP w0.127: CN6.20 v1(113.54,144.53) ; U4.C9 v5(82.81,136.09) ; v1(78.42,46.48) CN18.25
  L3_SIG w0.102: v1(113.54,144.53) 113.03,145.03 111.12,145.03 108.81,142.72 98.65,142.72 92.08,136.14 89.53,136.14 88.98,136.7 87.96,136.7 87.63,137.03 85.7,137.03 84.75,136.09 v5(82.81,136.09)
  BOTTOM w0.127: v1(78.42,46.48) 78.42,42.86 80.52,40.77 93.98,40.77 96.77,43.56 96.77,53.72 118.16,75.11 118.16,84.4 115.87,86.69 115.87,112.29 121.79,118.21 121.79,121.64 123.14,122.99 123.14,130.23 122.12,131.24 122.12,138.02 115.62,144.53 v1(113.54,144.53)
LCD_B3: length 184.5
  TOP w0.127: v1(78.36,47.88) 78.36,47.24 77.15,46.04 CN18.27 ; CN6.22 v1(113.54,143.26) ; U4.D10 v5(82.01,135.29)
  L3_SIG w0.102: v1(113.54,143.26) 112.9,143.89 110.87,143.89 109.32,142.34 98.78,142.34 92.2,135.76 88.16,135.76 87.15,136.78 85.98,136.78 84.93,135.73 82.45,135.73 v5(82.01,135.29)
  BOTTOM w0.127: v1(113.54,143.26) 116.3,143.26 121.87,137.69 121.87,131.14 121.89,131.11 121.89,128.32 122.86,127.36 122.86,123.19 121.41,121.74 121.41,118.34 115.6,112.52 115.6,86.49 117.75,84.33 117.75,75.34 96.27,53.85 96.27,43.69 93.85,41.27 80.77,41.27 79.38,42.67 79.38,46.86 v1(78.36,47.88)
LCD_B4: length 190.3
  TOP w0.127: R194.1 v1(76.58,46.48) 76.58,46.35 75.88,45.66 CN18.29 ; CN6.16 v1(113.54,147.07) ; U4.D8 v5(82.01,136.89)
  L3_SIG w0.102: v1(113.54,147.07) 112.9,147.7 111,147.7 108.64,145.34 95.5,145.34 92.13,141.96 90.7,141.96 88.57,139.83 86.03,139.83 84.96,138.76 84.96,137.03 84.73,136.8 83.62,136.8 83.13,137.29 82.41,137.29 v5(82.01,136.89)
  BOTTOM w0.127: v1(76.58,46.48) 76.58,43.94 80.26,40.26 94.36,40.26 97.29,43.19 97.29,52.57 113.16,68.43 113.16,69.22 118.62,74.68 118.62,84.45 116.97,86.11 116.97,96.14 116.51,96.6 116.51,111.91 123.39,118.8 123.39,130.56 122.51,131.43 122.51,138.3 116.42,144.4 116.42,144.99 114.35,147.07 v1(113.54,147.07)
LCD_B5: length 194.7
  TOP w0.127: v1(111.86,149.61) 111.86,149.15 111.05,148.34 CN6.13 ; CN18.31 74.61,46.14 v1(74.93,46.46) 75.06,46.58 R193.1 ; U4.D7 v5(81.21,138.49)
  L3_SIG w0.102: v5(81.21,138.49) 81.65,138.93 83.18,138.93 85.47,141.22 86.11,141.22 87.68,142.8 89.1,142.8 91.59,145.29 92.71,145.29 95.38,147.96 109.09,147.96 110.74,149.61 v1(111.86,149.61)
  BOTTOM w0.127: v1(74.93,46.46) 74.93,44.96 80.14,39.75 94.49,39.75 97.79,43.05 97.79,52.35 119.56,74.12 119.56,84.66 118.24,85.98 118.24,96.27 117.09,97.41 117.09,111.48 124,118.39 124,131.06 123.31,131.76 123.31,138.62 117.47,144.46 117.47,145.4 113.91,148.97 113.41,148.97 112.78,149.61 v1(111.86,149.61)
LCD_B6: length 195
  TOP w0.127: R192.1 73.79,47.12 v1(73.79,46.48) 73.79,45.97 73.34,45.53 CN18.33 ; CN6.12 v1(113.54,149.61) ; U4.C6 v5(82.81,139.29)
  L3_SIG w0.102: v5(82.81,139.29) 85.13,141.6 85.98,141.6 89.64,145.26 90.27,145.26 92.33,147.32 94.11,147.32 95.25,148.46 108.71,148.46 110.36,150.11 112.78,150.11 113.28,149.61 v1(113.54,149.61)
  BOTTOM w0.127: v1(113.54,149.61) 113.96,149.61 117.86,145.71 117.86,144.65 123.66,138.85 123.66,131.87 124.33,131.19 124.33,118.14 117.42,111.23 117.42,97.54 118.62,96.34 118.62,86.11 119.89,84.84 119.89,73.67 98.3,52.08 98.3,42.8 94.74,39.24 79.88,39.24 73.79,45.34 v1(73.79,46.48)
LCD_B7: length 201.1
  TOP w0.127: v1(111.94,150.55) 111.86,150.47 111.86,150.37 111.1,149.61 CN6.11 ; U4.C5 v5(82.81,140.09) ; R191.1 v1(72.64,46.48) 72.64,46.23 72.07,45.66 CN18.35
  L3_SIG w0.102: v5(82.81,140.09) 82.89,140.09 86.44,143.64 87.43,143.64 89.67,145.88 90.26,145.88 92.08,147.7 93.85,147.7 95.02,148.87 108.48,148.87 110.16,150.55 v1(111.94,150.55)
  BOTTOM w0.127: v1(111.94,150.55) 112.73,150.55 113.21,150.06 114.22,150.06 118.3,145.99 118.3,144.85 123.95,139.2 123.95,132.13 124.64,131.44 124.64,118.01 117.81,111.18 117.81,97.71 119,96.52 119,87 120.19,85.8 120.19,73.24 98.81,51.85 98.81,40.89 95.89,37.97 78.23,37.97 75.06,41.15 75.06,43.21 72.64,45.62 v1(72.64,46.48)
LCD_BL_CTRL: length 133.1
  TOP w0.127: v1(112.01,83.82) 97.41,83.82 97.03,84.2 97.03,85.47 97.82,86.26 CN15.53 ; CN18.43 66.99,42.74 v1(66.93,42.67)
  L3_SIG w0.102: v1(66.93,42.67) 68.07,41.53 78.36,41.53 109.79,72.96 109.79,74.96 111.91,77.08 111.91,83.72 v1(112.01,83.82)
  BOTTOM w0.127: v1(112.01,83.82) 112.01,90.07 110.62,91.47 110.62,108.28 111.86,109.52 111.86,114.55 117.75,120.45 117.75,121.51 116.99,122.28 116.99,123.04 SB80.1
LCD_G0: length 162
  TOP w0.127: v1(91.95,32.64) 92.39,33.08 CN18.4
  BOTTOM w0.127: v1(91.95,32.64) 74.47,32.64 68.83,38.28 68.83,47.62 70.04,48.83 70.04,49.21 69.6,49.66 65.15,49.66 62.1,52.7 62.1,62.1 53.54,70.66 53.54,81.33 45.21,89.66 45.21,106.68 40.03,111.86 40.03,124.01 37.34,126.71 37.34,131.32 38.86,132.84 43.39,132.84 43.65,133.1 44.83,133.1 45.59,133.86 45.59,135.76 44.25,137.11 44.25,138.53 43.69,139.09 43.69,139.95 43.94,140.21 44.96,140.21 45.47,139.7 SB51.1
LCD_G1: length 117
  TOP w0.127: v1(91.12,42.35) CN18.6
  BOTTOM w0.127: v1(91.12,42.35) 90.42,41.66 83.19,41.66 80.26,44.58 80.26,48.39 75.45,53.2 67.93,53.2 66.4,54.74 66.4,63.65 57.78,72.26 57.78,83.82 49.28,92.33 49.28,113.16 48.01,114.43 48.01,119.38 44.07,123.32 44.07,125.73 44.32,125.98 46.1,125.98
LCD_G2: length 193.4
  TOP w0.102: U4.G4 v5(79.61,140.89)
  TOP w0.127: v1(112.24,152.93) 112.14,152.93 112.06,153.01 110.4,153.01 CN6.5 ; v1(89.73,35.43) 89.85,35.56 CN18.8
  L3_SIG w0.102: v5(79.61,140.89) 79.8,140.89 80.24,141.33 80.56,141.33 80.85,141.62 80.85,144.29 84.87,148.31 84.88,148.31 85.49,148.92 87.96,148.92 88.65,149.61 88.65,149.73 92.15,153.24 110.16,153.24 110.46,152.93 v1(112.24,152.93)
  BOTTOM w0.127: v1(112.24,152.93) 112.42,152.93 112.9,153.42 114.3,153.42 114.81,152.91 114.81,152.15 125.86,141.1 125.86,117.09 120.9,112.14 120.9,98.17 120.65,97.92 120.65,88.39 122.56,86.49 122.56,73.66 100.84,51.94 100.84,39.24 97.03,35.43 v1(89.73,35.43)
LCD_G3: length 213.2
  TOP w0.127: CN18.10 88.58,35.65 v1(88.42,35.48) ; v1(111.86,147.07) 111.86,146.51 111.15,145.8 CN6.17 ; U4.C8 v5(82.81,136.89)
  L3_SIG w0.102: v5(82.81,136.89) 83.25,136.45 84.76,136.45 85.34,137.03 85.34,138.48 86.21,139.34 88.75,139.34 90.58,141.17 94.79,141.17 97.79,144.17 104.88,144.17 105.49,144.78 108.71,144.78 111,147.07 v1(111.86,147.07) 112.78,147.07 113.26,146.58 115.01,146.58 119.15,150.72 127.76,150.72 v1(128.27,151.23) ; v1(88.42,35.48) 89.15,36.22 110.36,36.22 113.03,38.89 113.03,53.47 114.05,54.48 114.05,74.65 118.36,78.97 118.36,88.39 123.77,93.8 125.58,93.8 127.36,95.58 127.36,96.49 132.51,101.65 132.51,104.62 v1(134.11,106.22)
  BOTTOM w0.127: v1(128.27,151.23) 130.81,148.69 130.81,129.36 133.73,126.44 133.73,125.25 135.08,123.9 135.08,120.47 133.53,118.92 133.53,106.81 133.93,106.41 133.93,106.41 v1(134.11,106.22)
LCD_G4: length 160.6
  TOP w0.127: CN18.12 v1(87.31,42.42) ; v1(113.51,141.02) 113.82,140.72 CN6.26 ; v5(87.07,135.31) 86.87,135.31 86.56,135.61 86.56,135.79 86.28,136.07 83.63,136.07 U4.B9
  L3_SIG w0.102: v1(113.51,141.02) 112.98,141.55 110.31,141.55 109.19,140.44 98.63,140.44 92.81,134.62 87.76,134.62 v5(87.07,135.31)
  BOTTOM w0.127: v1(87.31,42.42) 88.96,44.07 92.46,44.07 95.76,47.37 95.76,53.98 117.35,75.56 117.35,84.22 115.32,86.25 115.32,112.75 121.06,118.49 121.06,122.02 121.89,122.86 121.89,127.31 121.18,128.02 121.18,136.12 121.13,136.17 121.13,137.22 117.33,141.02 v1(113.51,141.02)
LCD_G5: length 145
  TOP w0.127: v1(85.79,31.19) 86.04,31.45 CN18.14
  L3_SIG w0.102: v1(36.3,126.31) 36.27,126.34 v1(36.27,137.79)
  BOTTOM w0.127: v1(36.27,137.79) 36.65,137.41 SB57.2 ; v1(85.79,31.19) 84.73,32.25 74.08,32.25 66.22,40.11 66.22,46.69 61.08,51.82 61.08,61.05 52.12,70.01 52.12,79.3 43.28,88.14 43.28,105.44 39.04,109.68 39.04,120.35 35.2,124.18 35.2,125.22 v1(36.3,126.31)
LCD_G6: length 165
  TOP w0.127: v1(84.52,31.18) 84.77,31.43 CN18.16
  L3_SIG w0.102: v1(35.18,123.06) 35.18,123.57 32.26,126.49 32.26,133.86 31.5,134.62 31.5,144.83 32.84,146.18 32.84,148.03 38.23,153.42 v1(39.5,153.42)
  BOTTOM w0.127: SB30.2 39.75,153.67 v1(39.5,153.42) ; v1(84.52,31.18) 84.52,31.22 83.98,31.75 73.63,31.75 65.79,39.6 65.79,46.51 60.6,51.69 60.6,60.88 50.9,70.59 50.9,78.82 42.77,86.94 42.77,105.31 38.58,109.5 38.58,120.04 35.56,123.06 v1(35.18,123.06)
LCD_G7: length 176.6
  TOP w0.127: CN18.18 83.5,31.43 v1(83.25,31.18)
  L3_SIG w0.102: v1(35.43,121.16) 35.41,121.16 34.09,122.48 34.09,122.68 31.5,125.27 31.5,130.3 30.86,130.94 30.86,134.62 31.11,134.87 31.11,144.96 32.56,146.41 32.56,149.02 41.15,157.61 46.86,157.61 v1(47.62,156.84)
  BOTTOM w0.127: v1(83.25,31.18) 72.56,31.18 65.34,38.39 65.34,46.32 60.22,51.44 60.22,60.73 50.52,70.43 50.52,78.66 42.39,86.79 42.39,105.15 38.2,109.34 38.2,119.41 36.45,121.16 v1(35.43,121.16) ; SB28.1 v1(47.62,156.84)
LCD_R0: length 130.5
  TOP w0.127: v1(92.46,48.13) 92.39,48.07 CN18.3 ; 95.12,142.24 103.5,142.24 106.81,138.94 v1(106.81,138.56)
  BOTTOM w0.127: v1(106.81,138.56) 106.81,135.89 108.33,134.37 118.08,134.37 119,133.45 119,122.56 119.25,122.3 119.25,118.59 114.07,113.41 114.07,84.05 115.32,82.8 115.32,74.78 92.46,51.92 v1(92.46,48.13)
LCD_R1: length 141.7
  TOP w0.127: CN18.5 91.12,48.7 87.38,52.45 v1(86.36,52.45) ; CN5.54 48.13,122.94 v1(49.15,123.95) 50.55,125.35 50.55,129.24 58.09,136.78 67.94,136.78 70.46,139.29 72.4,139.29 U4.R6
  BOTTOM w0.127: v1(49.15,123.95) 50.29,122.81 50.29,116.33 51.44,115.19 51.44,93.34 59.44,85.34 59.44,73.03 68.07,64.39 68.07,55.24 68.71,54.61 79.25,54.61 81.41,52.45 v1(86.36,52.45)
LCD_R2: length 137.5
  TOP w0.102: 71.63,137.92 72.64,137.92 U4.R7
  TOP w0.127: v1(85.47,51.69) 89.85,47.31 CN18.7 ; CN5.58 v1(48.84,120.4) 52.96,124.51 52.96,127.13 61.34,135.51 67.82,135.51 70.23,137.92 71.63,137.92
  BOTTOM w0.127: v1(85.47,51.69) 84.58,50.8 80.9,50.8 78.09,53.61 68.21,53.61 66.9,54.92 66.9,64.29 58.45,72.74 58.45,84.3 49.78,92.96 49.78,113.67 48.84,114.6 v1(48.84,120.4)
LCD_R3: length 226.7
  TOP w0.127: CN15.49 98.82,86.35 99.82,85.34 120.65,85.34 121.16,84.84 121.16,83.44 117.6,79.88 108.46,79.88 106.17,77.6 106.17,54.74 104.52,53.09 84.96,53.09 84.33,52.45 v1(84.33,51.82) 84.33,51.56 88.58,47.31 CN18.9 ; CN5.56 47.88,121.67 v1(49.15,122.94) 52.32,126.11 52.32,127.25 61.09,136.02 67.82,136.02 70.61,138.81 72.3,138.81 72.66,138.46 73.24,138.46 U4.P7
  BOTTOM w0.127: v1(49.15,122.94) 49.4,122.68 49.4,115.32 50.67,114.05 50.67,93.09 58.93,84.84 58.93,72.9 67.54,64.29 67.54,55.14 68.58,54.1 78.49,54.1 80.77,51.82 v1(84.33,51.82)
